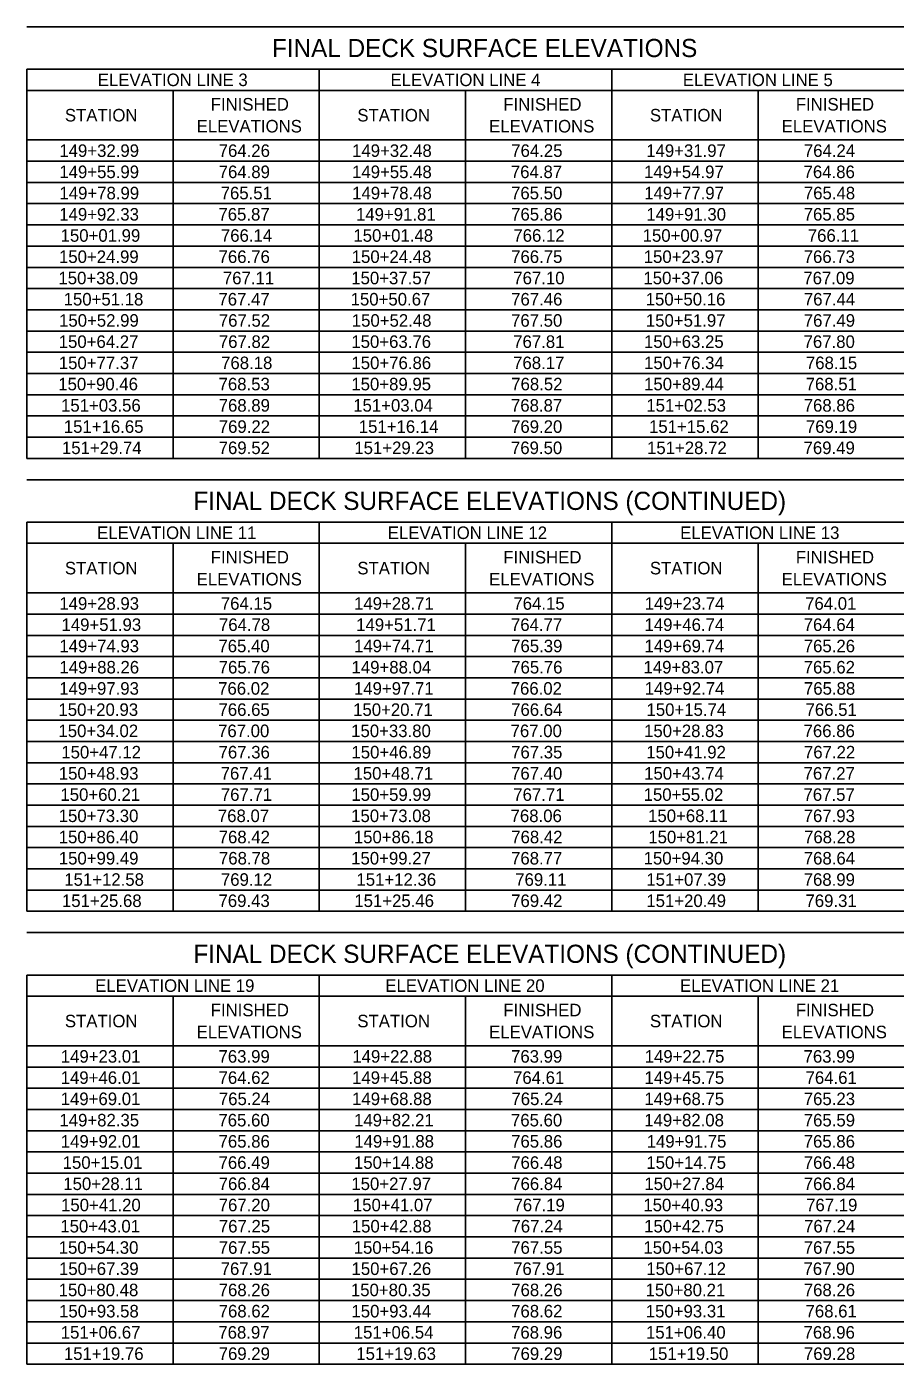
# Model space of a CAD drawing. Extents: x 2.7 to 33.4, y 1.1 to 21.
# Drawn here: x 12.24 to 21.94, y 6.06 to 21 of the extents above; entities that cross this region are included whole.
import ezdxf

# ---------------------------------------------------------------- set-up
doc = ezdxf.new("R2010")
doc.units = 0
doc.layers.add('BR_X_Beam_Object', color=7, linetype='Continuous')
doc.layers.add('BR_X_Slab_Object', color=7, linetype='Continuous')

msp = doc.modelspace()

# ---------------------------------------------------------------- linework, layer by layer
at = {"layer": 'BR_X_Slab_Object'}
for p, q in [((12.243, 21), (22.046, 21)), ((12.243, 20.526), (22.046, 20.526)), ((12.243, 20.526), (12.243, 19.735)), ((15.511, 20.526), (15.511, 19.735)), ((18.778, 20.526), (18.778, 19.735)), ((12.243, 20.288), (22.046, 20.288)), ((13.877, 20.288), (13.877, 19.735)), ((17.145, 20.288), (17.145, 19.735)), ((20.412, 20.288), (20.412, 19.735)), ((12.243, 19.735), (22.046, 19.735)), ((12.243, 19.735), (12.243, 18.549)), ((13.877, 19.735), (13.877, 18.549)), ((15.511, 19.735), (15.511, 18.549)), ((17.145, 19.735), (17.145, 18.549)), ((18.778, 19.735), (18.778, 18.549)), ((20.412, 19.735), (20.412, 18.549)), ((12.243, 19.498), (22.046, 19.498)), ((12.243, 19.261), (22.046, 19.261)), ((12.243, 19.024), (22.046, 19.024)), ((12.243, 18.786), (22.046, 18.786)), ((12.243, 18.549), (22.046, 18.549)), ((12.243, 18.549), (12.243, 18.312)), ((13.877, 18.549), (13.877, 18.312)), ((15.511, 18.549), (15.511, 18.312)), ((17.145, 18.549), (17.145, 18.312)), ((18.778, 18.549), (18.778, 18.312)), ((20.412, 18.549), (20.412, 18.312)), ((12.243, 18.312), (22.046, 18.312)), ((12.243, 18.312), (12.243, 17.6)), ((13.877, 18.312), (13.877, 17.6)), ((15.511, 18.312), (15.511, 17.6)), ((17.145, 18.312), (17.145, 17.6)), ((18.778, 18.312), (18.778, 17.6)), ((20.412, 18.312), (20.412, 17.6)), ((12.243, 18.075), (22.046, 18.075)), ((12.243, 17.838), (22.046, 17.838)), ((12.243, 17.6), (22.046, 17.6)), ((12.243, 17.6), (12.243, 17.126)), ((13.877, 17.6), (13.877, 17.126)), ((15.511, 17.6), (15.511, 17.126)), ((17.145, 17.6), (17.145, 17.126)), ((18.778, 17.6), (18.778, 17.126)), ((20.412, 17.6), (20.412, 17.126)), ((12.243, 17.363), (22.046, 17.363)), ((12.243, 17.126), (22.046, 17.126)), ((12.243, 17.126), (12.243, 16.415)), ((13.877, 17.126), (13.877, 16.415)), ((15.511, 17.126), (15.511, 16.415)), ((17.145, 17.126), (17.145, 16.415)), ((18.778, 17.126), (18.778, 16.415)), ((20.412, 17.126), (20.412, 16.415)), ((12.243, 16.889), (22.046, 16.889)), ((12.243, 16.652), (22.046, 16.652)), ((12.243, 16.415), (22.046, 16.415)), ((12.243, 16.415), (12.243, 16.177)), ((13.877, 16.415), (13.877, 16.177)), ((15.511, 16.415), (15.511, 16.177)), ((17.145, 16.415), (17.145, 16.177)), ((18.778, 16.415), (18.778, 16.177)), ((20.412, 16.415), (20.412, 16.177)), ((12.243, 16.177), (22.046, 16.177)), ((12.243, 15.94), (22.046, 15.94)), ((12.243, 15.466), (22.046, 15.466)), ((12.243, 15.466), (12.243, 14.952)), ((15.511, 15.466), (15.511, 14.952)), ((18.778, 15.466), (18.778, 14.952)), ((12.243, 15.229), (22.046, 15.229)), ((13.877, 15.229), (13.877, 14.952)), ((17.145, 15.229), (17.145, 14.952)), ((20.412, 15.229), (20.412, 14.952)), ((12.243, 14.952), (12.243, 14.201)), ((13.877, 14.952), (13.877, 14.201)), ((15.511, 14.952), (15.511, 14.201)), ((17.145, 14.952), (17.145, 14.201)), ((18.778, 14.952), (18.778, 14.201)), ((20.412, 14.952), (20.412, 14.201)), ((12.243, 14.675), (22.046, 14.675)), ((12.243, 14.438), (22.046, 14.438)), ((12.243, 14.201), (22.046, 14.201)), ((12.243, 14.201), (12.243, 13.015)), ((13.877, 14.201), (13.877, 13.015)), ((15.511, 14.201), (15.511, 13.015)), ((17.145, 14.201), (17.145, 13.015)), ((18.778, 14.201), (18.778, 13.015)), ((20.412, 14.201), (20.412, 13.015)), ((12.243, 13.964), (22.046, 13.964)), ((12.243, 13.727), (22.046, 13.727)), ((12.243, 13.489), (22.046, 13.489)), ((12.243, 13.252), (22.046, 13.252)), ((12.243, 13.015), (22.046, 13.015)), ((12.243, 13.015), (12.243, 11.829)), ((13.877, 13.015), (13.877, 11.829)), ((15.511, 13.015), (15.511, 11.829)), ((17.145, 13.015), (17.145, 11.829)), ((18.778, 13.015), (18.778, 11.829)), ((20.412, 13.015), (20.412, 11.829)), ((12.243, 12.778), (22.046, 12.778)), ((12.243, 12.541), (22.046, 12.541)), ((12.243, 12.304), (22.046, 12.304)), ((12.243, 12.066), (22.046, 12.066)), ((12.243, 11.829), (22.046, 11.829)), ((12.243, 11.829), (12.243, 11.118)), ((13.877, 11.829), (13.877, 11.118)), ((15.511, 11.829), (15.511, 11.118)), ((17.145, 11.829), (17.145, 11.118)), ((18.778, 11.829), (18.778, 11.118)), ((20.412, 11.829), (20.412, 11.118)), ((12.243, 11.592), (22.046, 11.592)), ((12.243, 11.355), (22.046, 11.355)), ((12.243, 11.118), (22.046, 11.118)), ((12.243, 10.88), (22.046, 10.88)), ((12.243, 10.406), (22.046, 10.406)), ((12.243, 10.406), (12.243, 8.904)), ((15.511, 10.406), (15.511, 8.904)), ((18.778, 10.406), (18.778, 8.904)), ((12.243, 10.169), (22.046, 10.169)), ((13.877, 10.169), (13.877, 8.904)), ((17.145, 10.169), (17.145, 8.904)), ((20.412, 10.169), (20.412, 8.904)), ((12.243, 9.616), (22.046, 9.616)), ((12.243, 9.378), (22.046, 9.378)), ((12.243, 9.141), (22.046, 9.141)), ((12.243, 8.904), (22.046, 8.904)), ((12.243, 8.904), (12.243, 8.43)), ((13.877, 8.904), (13.877, 8.43)), ((15.511, 8.904), (15.511, 8.43)), ((17.145, 8.904), (17.145, 8.43)), ((18.778, 8.904), (18.778, 8.43)), ((20.412, 8.904), (20.412, 8.43)), ((12.243, 8.667), (22.046, 8.667)), ((12.243, 8.43), (22.046, 8.43)), ((12.243, 8.43), (12.243, 7.718)), ((13.877, 8.43), (13.877, 7.718)), ((15.511, 8.43), (15.511, 7.718)), ((17.145, 8.43), (17.145, 7.718)), ((18.778, 8.43), (18.778, 7.718)), ((20.412, 8.43), (20.412, 7.718)), ((12.243, 8.192), (22.046, 8.192)), ((12.243, 7.955), (22.046, 7.955)), ((12.243, 7.718), (22.046, 7.718)), ((12.243, 7.718), (12.243, 7.244)), ((13.877, 7.718), (13.877, 7.244)), ((15.511, 7.718), (15.511, 7.244)), ((17.145, 7.718), (17.145, 7.244)), ((18.778, 7.718), (18.778, 7.244)), ((20.412, 7.718), (20.412, 7.244)), ((12.243, 7.481), (22.046, 7.481)), ((12.243, 7.244), (22.046, 7.244)), ((12.243, 7.244), (12.243, 6.532)), ((13.877, 7.244), (13.877, 6.532)), ((15.511, 7.244), (15.511, 6.532)), ((17.145, 7.244), (17.145, 6.532)), ((18.778, 7.244), (18.778, 6.532)), ((20.412, 7.244), (20.412, 6.532)), ((12.243, 7.007), (22.046, 7.007)), ((12.243, 6.769), (22.046, 6.769)), ((12.243, 6.532), (22.046, 6.532)), ((12.243, 6.532), (12.243, 6.058)), ((13.877, 6.532), (13.877, 6.058)), ((15.511, 6.532), (15.511, 6.058)), ((17.145, 6.532), (17.145, 6.058)), ((18.778, 6.532), (18.778, 6.058)), ((20.412, 6.532), (20.412, 6.058)), ((12.243, 6.295), (22.046, 6.295)), ((12.243, 6.058), (22.046, 6.058))]:
    msp.add_line(p, q, dxfattribs=at)

# ---------------------------------------------------------------- texts
at = {"layer": 'BR_X_Beam_Object'}
for s, height, p in [('FINAL DECK SURFACE ELEVATIONS', 0.203, (14.982, 20.661)), ('ELEVATION LINE 3', 0.14, (13.036, 20.337)), ('ELEVATION LINE 4', 0.14, (16.306, 20.337)), ('ELEVATION LINE 5', 0.14, (19.572, 20.337)), ('FINISHED', 0.14, (14.298, 20.064)), ('FINISHED', 0.14, (17.566, 20.064)), ('FINISHED', 0.14, (20.834, 20.064)), ('STATION', 0.14, (12.669, 19.942)), ('STATION', 0.14, (15.936, 19.942)), ('STATION', 0.14, (19.204, 19.942)), ('ELEVATIONS', 0.14, (14.141, 19.819)), ('ELEVATIONS', 0.14, (17.408, 19.819)), ('ELEVATIONS', 0.14, (20.676, 19.819)), ('149+32.99', 0.14, (12.607, 19.546)), ('764.26', 0.14, (14.387, 19.546)), ('149+32.48', 0.14, (15.877, 19.546)), ('764.25', 0.14, (17.655, 19.546)), ('149+31.97', 0.14, (19.163, 19.546)), ('764.24', 0.14, (20.924, 19.546)), ('149+55.99', 0.14, (12.607, 19.309)), ('764.89', 0.14, (14.387, 19.309)), ('149+55.48', 0.14, (15.877, 19.309)), ('764.87', 0.14, (17.651, 19.309)), ('149+54.97', 0.14, (19.139, 19.309)), ('764.86', 0.14, (20.921, 19.309)), ('149+78.99', 0.14, (12.608, 19.072)), ('765.51', 0.14, (14.409, 19.072)), ('149+78.48', 0.14, (15.878, 19.072)), ('765.50', 0.14, (17.653, 19.072)), ('149+77.97', 0.14, (19.141, 19.072)), ('765.48', 0.14, (20.924, 19.072)), ('149+92.33', 0.14, (12.606, 18.835)), ('765.87', 0.14, (14.384, 18.835)), ('149+91.81', 0.14, (15.921, 18.835)), ('765.86', 0.14, (17.654, 18.835)), ('149+91.30', 0.14, (19.164, 18.835)), ('765.85', 0.14, (20.922, 18.835)), ('150+01.99', 0.14, (12.621, 18.598)), ('766.14', 0.14, (14.412, 18.598)), ('150+01.48', 0.14, (15.892, 18.598)), ('766.12', 0.14, (17.679, 18.598)), ('150+00.97', 0.14, (19.123, 18.598)), ('766.11', 0.14, (20.968, 18.598)), ('150+24.99', 0.14, (12.603, 18.361)), ('766.76', 0.14, (14.386, 18.361)), ('150+24.48', 0.14, (15.873, 18.361)), ('766.75', 0.14, (17.654, 18.361)), ('150+23.97', 0.14, (19.135, 18.361)), ('766.73', 0.14, (20.922, 18.361)), ('150+38.09', 0.14, (12.597, 18.123)), ('767.11', 0.14, (14.434, 18.123)), ('150+37.57', 0.14, (15.868, 18.123)), ('767.10', 0.14, (17.678, 18.123)), ('150+37.06', 0.14, (19.132, 18.123)), ('767.09', 0.14, (20.918, 18.123)), ('150+51.18', 0.14, (12.655, 17.886)), ('767.47', 0.14, (14.384, 17.886)), ('150+50.67', 0.14, (15.861, 17.886)), ('767.46', 0.14, (17.654, 17.886)), ('150+50.16', 0.14, (19.157, 17.886)), ('767.44', 0.14, (20.924, 17.886)), ('150+52.99', 0.14, (12.604, 17.649)), ('767.52', 0.14, (14.389, 17.649)), ('150+52.48', 0.14, (15.874, 17.649)), ('767.50', 0.14, (17.653, 17.649)), ('150+51.97', 0.14, (19.159, 17.649)), ('767.49', 0.14, (20.923, 17.649)), ('150+64.27', 0.14, (12.6, 17.412)), ('767.82', 0.14, (14.389, 17.412)), ('150+63.76', 0.14, (15.869, 17.412)), ('767.81', 0.14, (17.677, 17.412)), ('150+63.25', 0.14, (19.138, 17.412)), ('767.80', 0.14, (20.921, 17.412)), ('150+77.37', 0.14, (12.601, 17.175)), ('768.18', 0.14, (14.414, 17.175)), ('150+76.86', 0.14, (15.87, 17.175)), ('768.17', 0.14, (17.676, 17.175)), ('150+76.34', 0.14, (19.139, 17.175)), ('768.15', 0.14, (20.947, 17.175)), ('150+90.46', 0.14, (12.595, 16.938)), ('768.53', 0.14, (14.386, 16.938)), ('150+89.95', 0.14, (15.869, 16.938)), ('768.52', 0.14, (17.655, 16.938)), ('150+89.44', 0.14, (19.139, 16.938)), ('768.51', 0.14, (20.944, 16.938)), ('151+03.56', 0.14, (12.626, 16.7)), ('768.89', 0.14, (14.387, 16.7)), ('151+03.04', 0.14, (15.89, 16.7)), ('768.87', 0.14, (17.652, 16.7)), ('151+02.53', 0.14, (19.164, 16.7)), ('768.86', 0.14, (20.922, 16.7)), ('151+16.65', 0.14, (12.657, 16.463)), ('769.22', 0.14, (14.388, 16.463)), ('151+16.14', 0.14, (15.952, 16.463)), ('769.20', 0.14, (17.653, 16.463)), ('151+15.62', 0.14, (19.194, 16.463)), ('769.19', 0.14, (20.947, 16.463)), ('151+29.74', 0.14, (12.636, 16.226)), ('769.52', 0.14, (14.387, 16.226)), ('151+29.23', 0.14, (15.902, 16.226)), ('769.50', 0.14, (17.652, 16.226)), ('151+28.72', 0.14, (19.172, 16.226)), ('769.49', 0.14, (20.921, 16.226)), ('FINAL DECK SURFACE ELEVATIONS (CONTINUED)', 0.203, (14.104, 15.602)), ('ELEVATION LINE 11', 0.14, (13.029, 15.277)), ('ELEVATION LINE 12', 0.14, (16.276, 15.277)), ('ELEVATION LINE 13', 0.14, (19.542, 15.277)), ('FINISHED', 0.14, (14.298, 15.004)), ('FINISHED', 0.14, (17.566, 15.004)), ('FINISHED', 0.14, (20.834, 15.004)), ('STATION', 0.14, (12.669, 14.882)), ('STATION', 0.14, (15.936, 14.882)), ('STATION', 0.14, (19.204, 14.882)), ('ELEVATIONS', 0.14, (14.141, 14.759)), ('ELEVATIONS', 0.14, (17.408, 14.759)), ('ELEVATIONS', 0.14, (20.676, 14.759)), ('149+28.93', 0.14, (12.607, 14.487)), ('764.15', 0.14, (14.411, 14.487)), ('149+28.71', 0.14, (15.899, 14.487)), ('764.15', 0.14, (17.679, 14.487)), ('149+23.74', 0.14, (19.146, 14.487)), ('764.01', 0.14, (20.938, 14.487)), ('149+51.93', 0.14, (12.631, 14.25)), ('764.78', 0.14, (14.39, 14.25)), ('149+51.71', 0.14, (15.923, 14.25)), ('764.77', 0.14, (17.652, 14.25)), ('149+46.74', 0.14, (19.144, 14.25)), ('764.64', 0.14, (20.922, 14.25)), ('149+74.93', 0.14, (12.607, 14.012)), ('765.40', 0.14, (14.384, 14.012)), ('149+74.71', 0.14, (15.899, 14.012)), ('765.39', 0.14, (17.654, 14.012)), ('149+69.74', 0.14, (19.144, 14.012)), ('765.26', 0.14, (20.923, 14.012)), ('149+88.26', 0.14, (12.608, 13.775)), ('765.76', 0.14, (14.387, 13.775)), ('149+88.04', 0.14, (15.871, 13.775)), ('765.76', 0.14, (17.655, 13.775)), ('149+83.07', 0.14, (19.133, 13.775)), ('765.62', 0.14, (20.922, 13.775)), ('149+97.93', 0.14, (12.606, 13.538)), ('766.02', 0.14, (14.381, 13.538)), ('149+97.71', 0.14, (15.898, 13.538)), ('766.02', 0.14, (17.649, 13.538)), ('149+92.74', 0.14, (19.146, 13.538)), ('765.88', 0.14, (20.925, 13.538)), ('150+20.93', 0.14, (12.597, 13.301)), ('766.65', 0.14, (14.385, 13.301)), ('150+20.71', 0.14, (15.889, 13.301)), ('766.64', 0.14, (17.654, 13.301)), ('150+15.74', 0.14, (19.166, 13.301)), ('766.51', 0.14, (20.943, 13.301)), ('150+34.02', 0.14, (12.597, 13.064)), ('767.00', 0.14, (14.38, 13.064)), ('150+33.80', 0.14, (15.867, 13.064)), ('767.00', 0.14, (17.648, 13.064)), ('150+28.83', 0.14, (19.139, 13.064)), ('766.86', 0.14, (20.921, 13.064)), ('150+47.12', 0.14, (12.629, 12.826)), ('767.36', 0.14, (14.386, 12.826)), ('150+46.89', 0.14, (15.87, 12.826)), ('767.35', 0.14, (17.654, 12.826)), ('150+41.92', 0.14, (19.163, 12.826)), ('767.22', 0.14, (20.925, 12.826)), ('150+48.93', 0.14, (12.601, 12.589)), ('767.41', 0.14, (14.409, 12.589)), ('150+48.71', 0.14, (15.893, 12.589)), ('767.40', 0.14, (17.653, 12.589)), ('150+43.74', 0.14, (19.14, 12.589)), ('767.27', 0.14, (20.921, 12.589)), ('150+60.21', 0.14, (12.619, 12.352)), ('767.71', 0.14, (14.411, 12.352)), ('150+59.99', 0.14, (15.869, 12.352)), ('767.71', 0.14, (17.678, 12.352)), ('150+55.02', 0.14, (19.134, 12.352)), ('767.57', 0.14, (20.92, 12.352)), ('150+73.30', 0.14, (12.6, 12.115)), ('768.07', 0.14, (14.378, 12.115)), ('150+73.08', 0.14, (15.867, 12.115)), ('768.06', 0.14, (17.648, 12.115)), ('150+68.11', 0.14, (19.184, 12.115)), ('767.93', 0.14, (20.922, 12.115)), ('150+86.40', 0.14, (12.6, 11.878)), ('768.42', 0.14, (14.387, 11.878)), ('150+86.18', 0.14, (15.897, 11.878)), ('768.42', 0.14, (17.655, 11.878)), ('150+81.21', 0.14, (19.186, 11.878)), ('768.28', 0.14, (20.926, 11.878)), ('150+99.49', 0.14, (12.601, 11.641)), ('768.78', 0.14, (14.39, 11.641)), ('150+99.27', 0.14, (15.867, 11.641)), ('768.77', 0.14, (17.653, 11.641)), ('150+94.30', 0.14, (19.134, 11.641)), ('768.64', 0.14, (20.923, 11.641)), ('151+12.58', 0.14, (12.662, 11.403)), ('769.12', 0.14, (14.412, 11.403)), ('151+12.36', 0.14, (15.926, 11.403)), ('769.11', 0.14, (17.7, 11.403)), ('151+07.39', 0.14, (19.164, 11.403)), ('768.99', 0.14, (20.922, 11.403)), ('151+25.68', 0.14, (12.636, 11.166)), ('769.43', 0.14, (14.385, 11.166)), ('151+25.46', 0.14, (15.902, 11.166)), ('769.42', 0.14, (17.654, 11.166)), ('151+20.49', 0.14, (19.164, 11.166)), ('769.31', 0.14, (20.942, 11.166)), ('FINAL DECK SURFACE ELEVATIONS (CONTINUED)', 0.203, (14.104, 10.542)), ('ELEVATION LINE 19', 0.14, (13.007, 10.218)), ('ELEVATION LINE 20', 0.14, (16.249, 10.218)), ('ELEVATION LINE 21', 0.14, (19.54, 10.218)), ('FINISHED', 0.14, (14.298, 9.945)), ('FINISHED', 0.14, (17.566, 9.945)), ('FINISHED', 0.14, (20.834, 9.945)), ('STATION', 0.14, (12.669, 9.822)), ('STATION', 0.14, (15.936, 9.822)), ('STATION', 0.14, (19.204, 9.822)), ('ELEVATIONS', 0.14, (14.141, 9.7)), ('ELEVATIONS', 0.14, (17.408, 9.7)), ('ELEVATIONS', 0.14, (20.676, 9.7)), ('149+23.01', 0.14, (12.623, 9.427)), ('763.99', 0.14, (14.385, 9.427)), ('149+22.88', 0.14, (15.88, 9.427)), ('763.99', 0.14, (17.653, 9.427)), ('149+22.75', 0.14, (19.146, 9.427)), ('763.99', 0.14, (20.921, 9.427)), ('149+46.01', 0.14, (12.622, 9.19)), ('764.62', 0.14, (14.386, 9.19)), ('149+45.88', 0.14, (15.877, 9.19)), ('764.61', 0.14, (17.675, 9.19)), ('149+45.75', 0.14, (19.144, 9.19)), ('764.61', 0.14, (20.943, 9.19)), ('149+69.01', 0.14, (12.622, 8.953)), ('765.24', 0.14, (14.389, 8.953)), ('149+68.88', 0.14, (15.877, 8.953)), ('765.24', 0.14, (17.657, 8.953)), ('149+68.75', 0.14, (19.143, 8.953)), ('765.23', 0.14, (20.923, 8.953)), ('149+82.35', 0.14, (12.608, 8.715)), ('765.60', 0.14, (14.384, 8.715)), ('149+82.21', 0.14, (15.899, 8.715)), ('765.60', 0.14, (17.652, 8.715)), ('149+82.08', 0.14, (19.141, 8.715)), ('765.59', 0.14, (20.923, 8.715)), ('149+92.01', 0.14, (12.623, 8.478)), ('765.86', 0.14, (14.386, 8.478)), ('149+91.88', 0.14, (15.902, 8.478)), ('765.86', 0.14, (17.654, 8.478)), ('149+91.75', 0.14, (19.168, 8.478)), ('765.86', 0.14, (20.922, 8.478)), ('150+15.01', 0.14, (12.644, 8.241)), ('766.49', 0.14, (14.386, 8.241)), ('150+14.88', 0.14, (15.898, 8.241)), ('766.48', 0.14, (17.655, 8.241)), ('150+14.75', 0.14, (19.164, 8.241)), ('766.48', 0.14, (20.923, 8.241)), ('150+28.11', 0.14, (12.651, 8.004)), ('766.84', 0.14, (14.387, 8.004)), ('150+27.97', 0.14, (15.869, 8.004)), ('766.84', 0.14, (17.655, 8.004)), ('150+27.84', 0.14, (19.142, 8.004)), ('766.84', 0.14, (20.923, 8.004)), ('150+41.20', 0.14, (12.626, 7.767)), ('767.20', 0.14, (14.387, 7.767)), ('150+41.07', 0.14, (15.886, 7.767)), ('767.19', 0.14, (17.681, 7.767)), ('150+40.93', 0.14, (19.131, 7.767)), ('767.19', 0.14, (20.949, 7.767)), ('150+43.01', 0.14, (12.618, 7.53)), ('767.25', 0.14, (14.389, 7.53)), ('150+42.88', 0.14, (15.874, 7.53)), ('767.24', 0.14, (17.658, 7.53)), ('150+42.75', 0.14, (19.14, 7.53)), ('767.24', 0.14, (20.926, 7.53)), ('150+54.30', 0.14, (12.6, 7.292)), ('767.55', 0.14, (14.388, 7.292)), ('150+54.16', 0.14, (15.895, 7.292)), ('767.55', 0.14, (17.655, 7.292)), ('150+54.03', 0.14, (19.132, 7.292)), ('767.55', 0.14, (20.923, 7.292)), ('150+67.39', 0.14, (12.603, 7.055)), ('767.91', 0.14, (14.409, 7.055)), ('150+67.26', 0.14, (15.871, 7.055)), ('767.91', 0.14, (17.676, 7.055)), ('150+67.12', 0.14, (19.164, 7.055)), ('767.90', 0.14, (20.92, 7.055)), ('150+80.48', 0.14, (12.599, 6.818)), ('768.26', 0.14, (14.387, 6.818)), ('150+80.35', 0.14, (15.864, 6.818)), ('768.26', 0.14, (17.655, 6.818)), ('150+80.21', 0.14, (19.156, 6.818)), ('768.26', 0.14, (20.923, 6.818)), ('150+93.58', 0.14, (12.604, 6.581)), ('768.62', 0.14, (14.387, 6.581)), ('150+93.44', 0.14, (15.87, 6.581)), ('768.62', 0.14, (17.654, 6.581)), ('150+93.31', 0.14, (19.158, 6.581)), ('768.61', 0.14, (20.943, 6.581)), ('151+06.67', 0.14, (12.623, 6.344)), ('768.97', 0.14, (14.383, 6.344)), ('151+06.54', 0.14, (15.896, 6.344)), ('768.96', 0.14, (17.653, 6.344)), ('151+06.40', 0.14, (19.16, 6.344)), ('768.96', 0.14, (20.921, 6.344)), ('151+19.76', 0.14, (12.658, 6.106)), ('769.29', 0.14, (14.387, 6.106)), ('151+19.63', 0.14, (15.924, 6.106)), ('769.29', 0.14, (17.655, 6.106)), ('151+19.50', 0.14, (19.191, 6.106)), ('769.28', 0.14, (20.925, 6.106))]:
    msp.add_text(s, height=height, dxfattribs=at).set_placement(p)

doc.saveas('drawing.dxf')
